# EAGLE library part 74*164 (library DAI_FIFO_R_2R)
8-bit parallel out SHIFT REGISTER
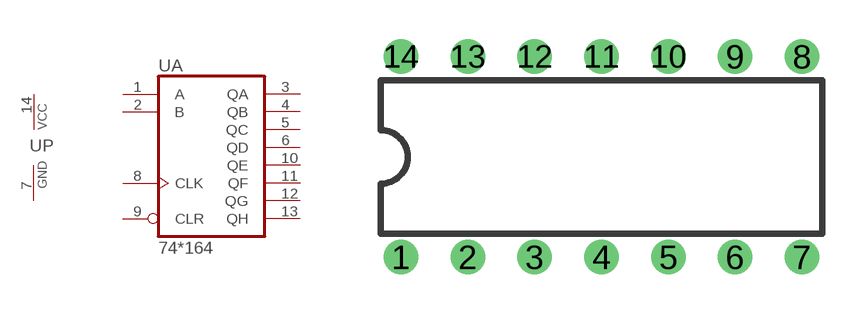
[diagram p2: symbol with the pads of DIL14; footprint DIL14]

Designator prefix U; gates A=74164 P=PWRN

## 74164N, 74AC164N, 74ACT164N, 74HC164N, 74HCT164N, 74LS164N  [DIL14]
1  A:A  in
2  A:B  in
3  A:QA  out
4  A:QB  out
5  A:QC  out
6  A:QD  out
7  P:GND  pwr
8  A:CLK  in
9  A:CLR  in
10  A:QE  out
11  A:QF  out
12  A:QG  out
13  A:QH  out
14  P:VCC  pwr

## Footprint DIL14 (pad centres in mm)
Dual In Line Package
drill 0.8 round: 1 -7.62,-3.81; 2 -5.08,-3.81; 3 -2.54,-3.81; 4 0,-3.81; 5 2.54,-3.81; 6 5.08,-3.81; 7 7.62,-3.81; 8 7.62,3.81; 9 5.08,3.81; 10 2.54,3.81; 11 0,3.81; 12 -2.54,3.81; 13 -5.08,3.81; 14 -7.62,3.81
